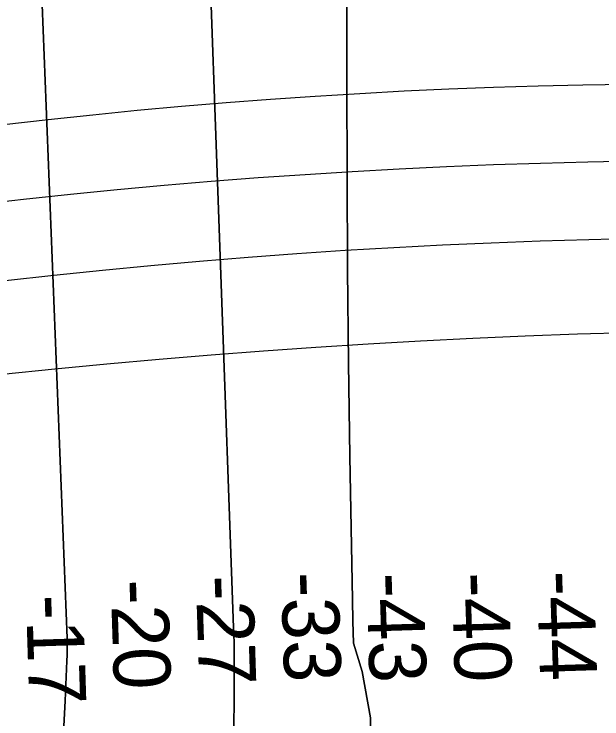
# Model space of a CAD drawing. Extents: x 3313447 to 3351316, y 703786 to 729172.
# Drawn here: x 3323027 to 3323716, y 726058 to 726885 of the extents above; entities that cross this region are included whole.
import ezdxf

# ---------------------------------------------------------------- set-up
doc = ezdxf.new("R2010")
doc.units = 0
for name, color, linetype in [('V-RIVR-RANG', 7, 'Continuous'), ('V-TOPO-DPTH', 7, 'Continuous'), ('V-TOPO-MINR', 7, 'Continuous'), ('V-UTIL-LINE', 7, 'Continuous')]:
    doc.layers.add(name, color=color, linetype=linetype)

msp = doc.modelspace()

# ---------------------------------------------------------------- linework, layer by layer
at = {"layer": 'V-TOPO-DPTH'}
for points in [[(3323439.27, 725767.72), (3323444.75, 726059.14), (3323435.03, 726113.76), (3323424.8, 726146.96), (3323424.16, 726172.63), (3323423.62, 726198.3), (3323420.64, 726366.17), (3323419.02, 726475.78), (3323417.82, 726585.4), (3323417.27, 726695.01), (3323417.14, 726804.64), (3323417.58, 727062.73)], [(3323417.58, 727062.73), (3323417.14, 726804.64), (3323417.27, 726695.01), (3323417.82, 726585.4), (3323419.02, 726475.78), (3323420.64, 726366.17), (3323423.62, 726198.3), (3323424.16, 726172.63), (3323424.8, 726146.96), (3323435.03, 726113.76), (3323444.75, 726059.14), (3323439.27, 725767.72)], [(3323230.81, 724551.57), (3323246.85, 725053.67), (3323248.45, 725103.47), (3323250.09, 725153.27), (3323251.75, 725203.07), (3323253.44, 725252.87), (3323254.42, 725281.31), (3323255.68, 725316.88), (3323256.98, 725352.46), (3323258.37, 725388.03), (3323259.8, 725423.6), (3323281.69, 725952.35), (3323282.84, 725984.49), (3323283.76, 726016.64), (3323284.32, 726048.79), (3323284.64, 726080.96), (3323284.9, 726136.2), (3323284.89, 726140.74), (3323284.85, 726145.28), (3323284.75, 726149.82), (3323284.61, 726154.36), (3323252.36, 727048.28)], [(3323252.36, 727048.28), (3323284.61, 726154.36), (3323284.75, 726149.82), (3323284.85, 726145.28), (3323284.89, 726140.74), (3323284.9, 726136.2), (3323284.64, 726080.96), (3323284.32, 726048.79), (3323283.76, 726016.64), (3323282.84, 725984.49), (3323281.69, 725952.35), (3323259.8, 725423.6), (3323258.37, 725388.03), (3323256.98, 725352.46), (3323255.68, 725316.88), (3323254.42, 725281.31), (3323253.44, 725252.87), (3323251.75, 725203.07), (3323250.09, 725153.27), (3323248.45, 725103.47), (3323246.85, 725053.67), (3323230.81, 724551.57)], [(3323084.91, 726049.38), (3323086.56, 726079.39), (3323088.65, 726126.19), (3323088.86, 726132.83), (3323088.96, 726139.47), (3323088.9, 726146.11), (3323088.72, 726152.75), (3323054.92, 727015.56)], [(3323054.92, 727015.56), (3323088.72, 726152.75), (3323088.9, 726146.11), (3323088.96, 726139.47), (3323088.86, 726132.83), (3323088.65, 726126.19), (3323086.56, 726079.39), (3323084.91, 726049.38)]]:
    msp.add_lwpolyline(points, dxfattribs=at)
at = {"layer": 'V-TOPO-MINR'}
for points in [[(3323439.27, 725767.72), (3323444.75, 726059.14), (3323435.03, 726113.76), (3323424.8, 726146.96), (3323424.16, 726172.63), (3323423.62, 726198.3), (3323420.64, 726366.17), (3323419.02, 726475.78), (3323417.82, 726585.4), (3323417.27, 726695.01), (3323417.14, 726804.64), (3323417.58, 727062.73)], [(3323252.36, 727048.28), (3323284.61, 726154.36), (3323284.75, 726149.82), (3323284.85, 726145.28), (3323284.89, 726140.74), (3323284.9, 726136.2), (3323284.64, 726080.96), (3323284.32, 726048.79), (3323283.76, 726016.64), (3323282.84, 725984.49), (3323281.69, 725952.35), (3323259.8, 725423.6), (3323258.37, 725388.03), (3323256.98, 725352.46), (3323255.68, 725316.88), (3323254.42, 725281.31), (3323253.44, 725252.87), (3323251.75, 725203.07), (3323250.09, 725153.27), (3323248.45, 725103.47), (3323246.85, 725053.67), (3323230.81, 724551.57)], [(3323054.92, 727015.56), (3323088.72, 726152.75), (3323088.9, 726146.11), (3323088.96, 726139.47), (3323088.86, 726132.83), (3323088.65, 726126.19), (3323086.56, 726079.39), (3323084.91, 726049.38)]]:
    msp.add_lwpolyline(points, dxfattribs=at)
at = {"layer": 'V-UTIL-LINE'}
for points in [[(3323014.7, 726755.51), (3323066.74, 726761.5), (3323118.83, 726767.08), (3323170.95, 726772.27), (3323223.12, 726777.06), (3323275.32, 726781.45), (3323327.55, 726785.44), (3323379.81, 726789.02), (3323432.1, 726792.2), (3323484.41, 726794.99), (3323536.73, 726797.37), (3323589.08, 726799.35), (3323641.44, 726800.92), (3323693.81, 726802.1), (3323746.19, 726802.87)], [(3322982.7, 726661.74), (3323037.64, 726668), (3323092.64, 726673.86), (3323147.67, 726679.32), (3323202.73, 726684.37), (3323257.84, 726689.03), (3323312.98, 726693.28), (3323368.15, 726697.13), (3323423.34, 726700.58), (3323478.56, 726703.63), (3323533.8, 726706.27), (3323589.05, 726708.52), (3323644.33, 726710.36), (3323699.61, 726711.79), (3323754.9, 726712.83)], [(3323016.59, 726572.73), (3323073.42, 726578.99), (3323130.3, 726584.83), (3323187.22, 726590.28), (3323244.17, 726595.31), (3323301.16, 726599.93), (3323358.18, 726604.14), (3323415.23, 726607.95), (3323472.31, 726611.35), (3323529.41, 726614.34), (3323586.53, 726616.92), (3323643.66, 726619.09), (3323700.81, 726620.85), (3323757.97, 726622.2)], [(3323013.14, 726462.67), (3323074.31, 726468.94), (3323135.51, 726474.81), (3323196.75, 726480.29), (3323258.03, 726485.37), (3323319.33, 726490.05), (3323380.67, 726494.33), (3323442.03, 726498.22), (3323503.42, 726501.7), (3323564.83, 726504.8), (3323626.25, 726507.49), (3323687.7, 726509.78), (3323749.15, 726511.68)]]:
    msp.add_lwpolyline(points, dxfattribs=at)

# ---------------------------------------------------------------- texts
at = {"layer": 'V-RIVR-RANG'}
for s, p in [('-33', (3323339.73, 726229.64)), ('-43', (3323439.8, 726228.86)), ('-40', (3323539.83, 726229.4)), ('-44', (3323639.82, 726231.26)), ('-20', (3323139.9, 726220.91)), ('-27', (3323239.8, 726225.67)), ('-17', (3323040.42, 726202.97))]:
    msp.add_text(s, height=67, rotation=271.81175, dxfattribs=at).set_placement(p)

doc.saveas('drawing.dxf')
